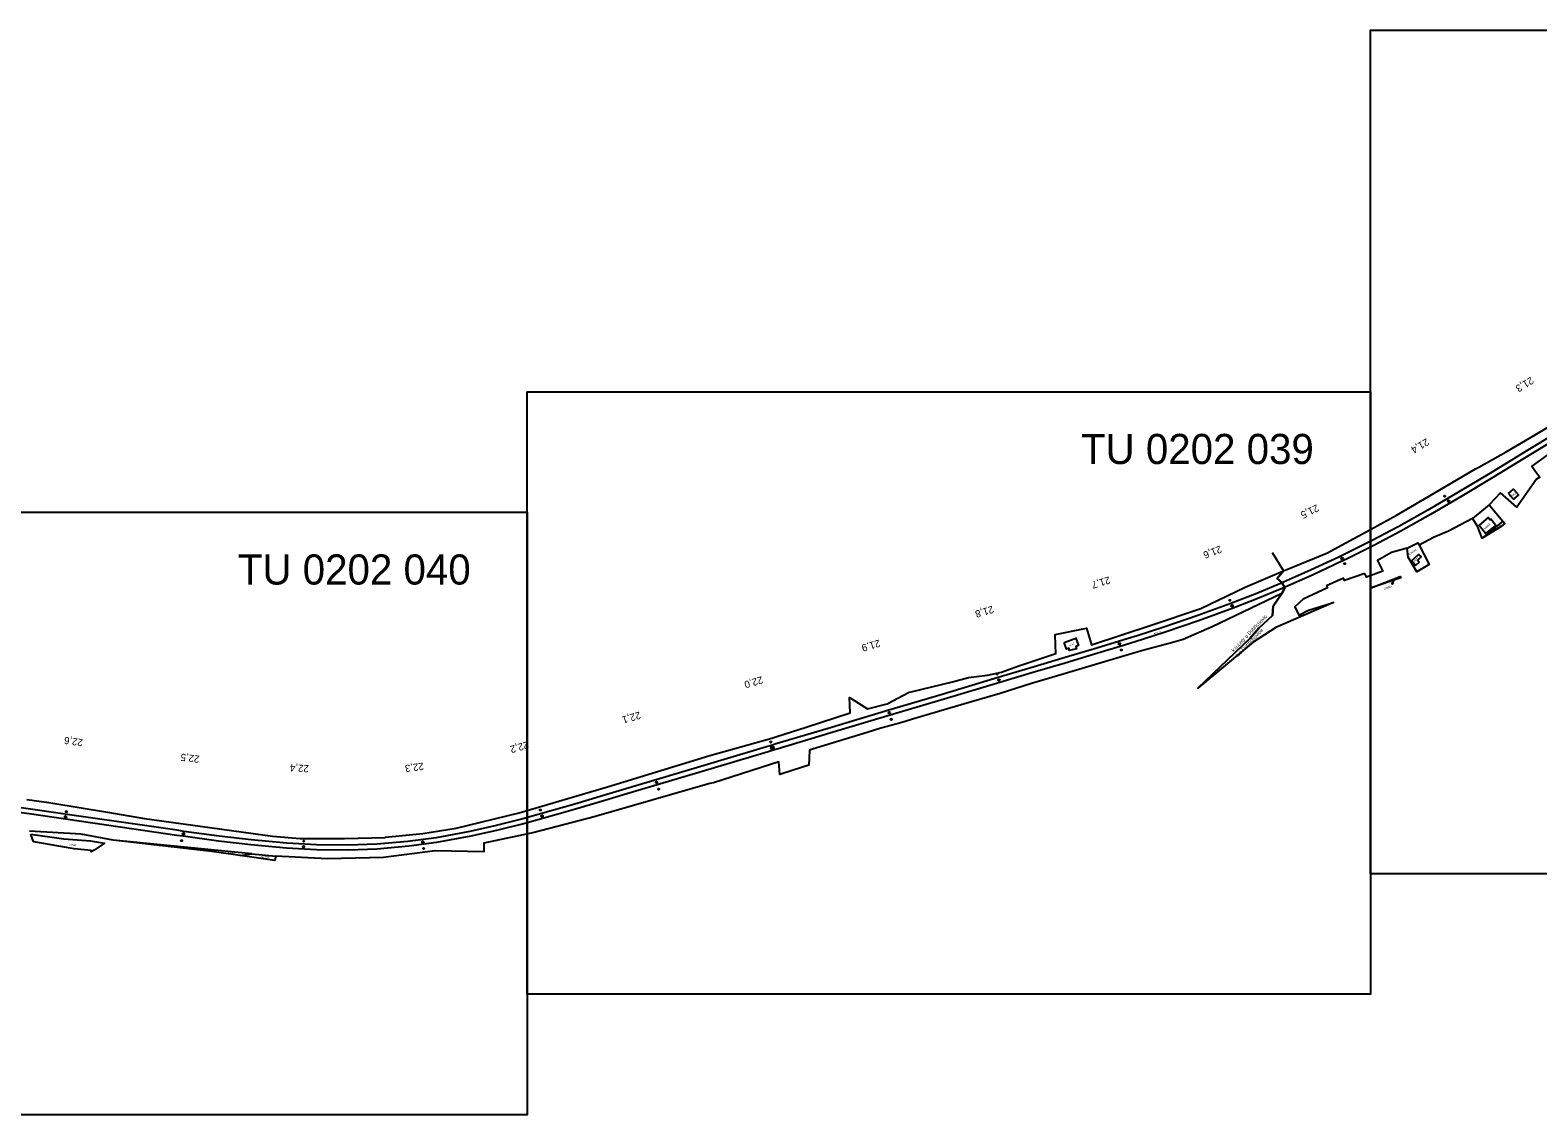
# Model space of a CAD drawing. Extents: x -768800 to -748700, y -1061452 to -1051366.
# Drawn here: x -757513 to -756261, y -1060400 to -1059500 of the extents above; entities that cross this region are included whole.
import ezdxf

# ---------------------------------------------------------------- set-up
doc = ezdxf.new("R2010")
doc.units = 0
for name, color, linetype in [('Vrstva 1', 7, 'Continuous'), ('Vrstva 2', 7, 'Continuous'), ('Vrstva 53', 7, 'Continuous'), ('Vrstva 54', 7, 'Continuous'), ('Vrstva 55', 7, 'Continuous'), ('Vrstva 57', 7, 'Continuous'), ('Vrstva 7', 7, 'Continuous')]:
    doc.layers.add(name, color=color, linetype=linetype)

msp = doc.modelspace()

# ---------------------------------------------------------------- linework, layer by layer
at = {"layer": 'Vrstva 1'}
for p, q in [((-756897.5, -1060093.5), (-756901.4, -1060094.6)), ((-756895.8, -1060097.4), (-756900.1, -1060098.7)), ((-757390.9, -1060168.1), (-757428.4, -1060162.7)), ((-757385.6, -1060168.8), (-757390.9, -1060168.1)), ((-757385.1, -1060164.8), (-757390.6, -1060163.9)), ((-757356.2, -1060172.9), (-757385.6, -1060168.8)), ((-757355.7, -1060168.7), (-757385.1, -1060164.8))]:
    msp.add_line(p, q, dxfattribs=at)
for points in [[(-756400, -1060200), (-756400, -1059500), (-755900, -1059500), (-755900, -1060200), (-756400, -1060200)], [(-757100, -1060300), (-757100, -1059800), (-756400, -1059800), (-756400, -1060300), (-757100, -1060300)], [(-756247.6, -1059835.2), (-756275.6, -1059852.3), (-756300.9, -1059867.8), (-756326, -1059882.9), (-756352.3, -1059898.3), (-756376.5, -1059911.8), (-756399.1, -1059923.7), (-756421.9, -1059935.1), (-756426.3, -1059937.3), (-756449.7, -1059948.2), (-756474.7, -1059959.2), (-756494.4, -1059967.4), (-756515.8, -1059975.8), (-756543.2, -1059985.8), (-756571.6, -1059995.4), (-756593.8, -1060002.5), (-756601.1, -1060004.8), (-756627.1, -1060012.7), (-756650.8, -1060019.8), (-756679.3, -1060028.3), (-756709.1, -1060037.2), (-756755.6, -1060051.1), (-756799.9, -1060064.3), (-756850.3, -1060079.4), (-756892.6, -1060092), (-756897.5, -1060093.5)], [(-756247.5, -1059840.2), (-756273.4, -1059856.1), (-756298.4, -1059871.3), (-756324.2, -1059886.8), (-756350.2, -1059902), (-756374.7, -1059915.6), (-756397.2, -1059927.5), (-756419.8, -1059938.9), (-756424.2, -1059941), (-756447.6, -1059952), (-756472.8, -1059963), (-756492.1, -1059971.1), (-756514.1, -1059979.7), (-756542.7, -1059990.1), (-756570.4, -1059999.5), (-756588.3, -1060005.2), (-756604.9, -1060010.5), (-756626.4, -1060017), (-756653.4, -1060025.1), (-756678.3, -1060032.5), (-756707.6, -1060041.2), (-756753.8, -1060055), (-756798.7, -1060068.4), (-756848.9, -1060083.4), (-756891.6, -1060096.2), (-756895.8, -1060097.4)], [(-757800, -1060400), (-757800, -1059900), (-757100, -1059900), (-757100, -1060400), (-757800, -1060400)], [(-756901.4, -1060094.6), (-756958.7, -1060111.8), (-757020.8, -1060130.3), (-757036.6, -1060135), (-757060.6, -1060142.2), (-757078.3, -1060147.3), (-757103.6, -1060154.4), (-757126.9, -1060160.3), (-757147.5, -1060164.9), (-757175.6, -1060170.1), (-757199, -1060173.2), (-757224.9, -1060175.4), (-757248.6, -1060176.3), (-757274.8, -1060176.1), (-757299.6, -1060174.7), (-757329.2, -1060171.9), (-757355.7, -1060168.7)], [(-757390.6, -1060163.9), (-757427.3, -1060158.6), (-757470.2, -1060152.4), (-757510.3, -1060146.7), (-757531.3, -1060143.7), (-757548.7, -1060141.1), (-757582.8, -1060136.1), (-757619.4, -1060130.7), (-757645.2, -1060126.9), (-757670, -1060123.2), (-757674.9, -1060122.5), (-757704.4, -1060118.1), (-757763.5, -1060109.4)], [(-756900.1, -1060098.7), (-756957.5, -1060115.9), (-757020, -1060134.5), (-757035.7, -1060139.2), (-757060, -1060146.4), (-757077.4, -1060151.4), (-757102.1, -1060158.2), (-757125.6, -1060164.2), (-757146.8, -1060168.9), (-757175.2, -1060174.1), (-757198.2, -1060177.2), (-757224.8, -1060179.5), (-757248.1, -1060180.4), (-757274.9, -1060180.2), (-757299.7, -1060178.8), (-757329.5, -1060176.1), (-757356.2, -1060172.9)], [(-757428.4, -1060162.7), (-757471.9, -1060156.4), (-757511.5, -1060150.6), (-757532, -1060147.7), (-757549.3, -1060145.2), (-757583.5, -1060140.2), (-757619.8, -1060135), (-757646.6, -1060131.2), (-757671.2, -1060127.6), (-757676, -1060126.9), (-757702.8, -1060123), (-757729.2, -1060119.2), (-757731.6, -1060118.9)]]:
    msp.add_lwpolyline(points, dxfattribs=at)
at = {"layer": 'Vrstva 53'}
for points in [[(-757515.4, -1060138.4), (-757497, -1060140.9), (-757493.9, -1060141.3), (-757450, -1060148.6), (-757417.7, -1060154), (-757387.6, -1060158.2), (-757311.4, -1060168.7), (-757288.5, -1060170.6), (-757251.8, -1060170.7), (-757218, -1060169.8), (-757217.6, -1060169.7), (-757186.6, -1060166.7), (-757158.9, -1060162.2), (-757106.6, -1060149.4), (-757033.3, -1060127.9), (-756948.4, -1060101.9), (-756896.9, -1060087.4), (-756892.9, -1060086.1), (-756868.3, -1060078.2), (-756832, -1060066.5), (-756832.6, -1060053.7), (-756817.6, -1060063.1), (-756801.3, -1060058.9), (-756782.8, -1060049.4), (-756781.2, -1060049), (-756747, -1060040.6), (-756733.8, -1060037), (-756717.8, -1060035.1), (-756706.2, -1060032.7), (-756704.1, -1060031.9), (-756691.8, -1060027.4), (-756661.2, -1060017.1), (-756661.4, -1060010.3), (-756661.7, -1060001.5), (-756635.8, -1059996.1), (-756631.7, -1060010), (-756582.1, -1059993.6), (-756540.9, -1059980), (-756504.1, -1059962.3), (-756472.3, -1059948.7), (-756469.5, -1059947.6), (-756435.8, -1059933.6), (-756424, -1059927.2), (-756399.9, -1059914.2), (-756377.8, -1059902.2), (-756347.1, -1059884.3), (-756312.9, -1059864.1), (-756310, -1059862.5), (-756287.4, -1059849.9), (-756263.4, -1059835.9), (-756241.4, -1059822.7)], [(-756253, -1059852.5), (-756266, -1059861.9), (-756263.5, -1059865.4), (-756259.5, -1059871), (-756262.1, -1059872.6), (-756278.4, -1059895.7), (-756292.1, -1059883.9), (-756301.4, -1059893.9), (-756290, -1059907.3), (-756288.5, -1059909.4), (-756291.4, -1059911.9), (-756307.2, -1059921.5), (-756311.1, -1059911.6), (-756315.3, -1059905.1), (-756335.1, -1059915.8), (-756347.6, -1059921), (-756359.7, -1059927.4), (-756351.2, -1059943.4), (-756361.5, -1059949.4), (-756368.7, -1059937.2), (-756369.6, -1059929.9), (-756382.5, -1059933.3), (-756394.1, -1059940), (-756389.7, -1059948.9), (-756403.3, -1059954), (-756404.6, -1059950.8)], [(-756404.6, -1059950.8), (-756421.6, -1059956.5), (-756422.4, -1059954.7), (-756436.5, -1059961.1), (-756435.8, -1059962.8), (-756455.9, -1059972), (-756462.9, -1059978.4), (-756459.4, -1059985.4), (-756451.4, -1059981.2), (-756430.7, -1059974.9), (-756478.6, -1059995.6), (-756497.3, -1060007.8), (-756543.3, -1060045.9), (-756500.1, -1060004.9), (-756492.8, -1059996.3), (-756481.4, -1059985.7), (-756480.8, -1059977.8), (-756473.5, -1059967.4), (-756531.5, -1059995.2), (-756555.6, -1060005.6), (-756565.3, -1060008.4), (-756590, -1060014.9), (-756630.9, -1060027.2), (-756655.1, -1060034.4), (-756681.4, -1060042.2), (-756707.5, -1060050.5)], [(-756399.5, -1059962.8), (-756375.3, -1059953.4), (-756374.8, -1059954.4), (-756399.5, -1059962.8)], [(-756707.5, -1060050.5), (-756739.7, -1060059.9), (-756780.2, -1060071.8), (-756787, -1060073.9), (-756794, -1060075.8), (-756806.5, -1060079.2), (-756817.9, -1060082.7), (-756830.4, -1060086.6), (-756863.1, -1060096.7), (-756865.8, -1060097.5), (-756866, -1060104), (-756866.2, -1060109.8), (-756879.1, -1060113.9), (-756890.4, -1060117.7), (-756891, -1060107.2), (-756945.3, -1060124.4), (-756948.3, -1060125.2), (-757044.3, -1060152.6), (-757094.3, -1060165.8), (-757135.9, -1060174.5), (-757136, -1060181.8), (-757176.4, -1060180.9), (-757219.2, -1060186.4), (-757265.9, -1060187.6), (-757308.7, -1060185.5), (-757309.5, -1060188.9), (-757338.3, -1060184.9), (-757361.9, -1060181.6), (-757443.6, -1060172), (-757470.4, -1060167), (-757513.1, -1060164.5)], [(-757512.1, -1060167.1), (-757484.7, -1060171), (-757462.5, -1060172.6), (-757451, -1060174.5), (-757459.6, -1060180.3), (-757462, -1060181.9), (-757461.9, -1060180.6), (-757476.1, -1060179.3), (-757509.6, -1060173.6), (-757510.3, -1060172.2), (-757512.1, -1060167.1)]]:
    msp.add_lwpolyline(points, dxfattribs=at)
at = {"layer": 'Vrstva 54'}
msp.add_line((-756380.8, -1059958.7), (-756381.9, -1059959.7), dxfattribs=at)
msp.add_lwpolyline([(-756380.6, -1059955.9), (-756381.9, -1059959.7), (-756382.2, -1059958.2)], dxfattribs=at)
at = {"layer": 'Vrstva 55'}
for p, q in [((-756301.4, -1059893.9), (-756315.3, -1059905.1)), ((-756290, -1059907.3), (-756307.2, -1059921.5)), ((-757328.6, -1060183.5), (-757443.6, -1060172))]:
    msp.add_line(p, q, dxfattribs=at)
for points in [[(-756285.4, -1059884.5), (-756281.2, -1059880.8), (-756277.1, -1059885.5), (-756281.3, -1059889.2), (-756285.4, -1059884.5)], [(-756304.1, -1059917.6), (-756295.9, -1059910.9), (-756300.1, -1059905.8), (-756300.8, -1059906.3), (-756302.3, -1059904.4), (-756309.9, -1059910.6), (-756304.1, -1059917.6)], [(-756481.7, -1059933.3), (-756472.3, -1059948.7), (-756477.5, -1059954.9), (-756473.5, -1059958.4), (-756471.1, -1059962.7)], [(-756369.6, -1059929.9), (-756360.6, -1059925.4), (-756359.7, -1059927.4)], [(-756366, -1059940.4), (-756360, -1059935.1), (-756357.8, -1059937.1), (-756360.8, -1059939.9), (-756359.5, -1059941.4), (-756362.7, -1059944.1), (-756366, -1059940.4)], [(-756473.5, -1059967.4), (-756471.1, -1059962.7), (-756473.5, -1059958.4), (-756477.5, -1059954.9), (-756472.3, -1059948.7)], [(-756471.1, -1059962.7), (-756473.5, -1059967.4), (-756480.8, -1059977.8), (-756481.4, -1059985.7), (-756492.8, -1059996.3), (-756500.1, -1060004.9), (-756543.3, -1060045.9)], [(-756654.3, -1060008), (-756644.6, -1060004.5), (-756642.4, -1060010.6), (-756644.5, -1060011.4), (-756643.9, -1060013.3), (-756649.8, -1060014.7), (-756650.4, -1060012.8), (-756652.3, -1060013.5), (-756654.3, -1060008)], [(-757338.3, -1060184.9), (-757328.6, -1060183.5), (-757308.7, -1060185.5)]]:
    msp.add_lwpolyline(points, dxfattribs=at)
at = {"layer": 'Vrstva 7'}
for p, q in [((-756338.3, -1059886.7), (-756338.4, -1059886.7)), ((-756421.3, -1059942.7), (-756421.4, -1059942.7)), ((-756516.7, -1059973.1), (-756516.8, -1059973.1)), ((-756606.8, -1060014.3), (-756606.9, -1060014.3)), ((-756709.8, -1060034.4), (-756709.9, -1060034.4)), ((-756797.7, -1060071.9), (-756797.8, -1060071.9)), ((-756897.8, -1060090.7), (-756897.9, -1060090.7)), ((-756990.8, -1060129.8), (-756990.9, -1060129.8)), ((-757482.6, -1060148.4), (-757482.7, -1060148.4)), ((-757089.1, -1060147), (-757089.2, -1060147.1)), ((-757386.9, -1060172.5), (-757387, -1060172.5)), ((-757285.3, -1060172.9), (-757285.4, -1060172.9)), ((-757185.9, -1060179), (-757186, -1060179))]:
    msp.add_line(p, q, dxfattribs=at)
for centre, radius in [((-756338.4, -1059886.7), 0.5), ((-756335.1, -1059890.8), 0.75), ((-756423.5, -1059938.3), 0.75), ((-756421.4, -1059942.7), 0.5), ((-756516.7, -1059973.1), 0.5), ((-756514.9, -1059977.7), 0.75), ((-756608.4, -1060009.3), 0.75), ((-756606.8, -1060014.3), 0.5), ((-756709.9, -1060034.4), 0.5), ((-756708.4, -1060039.2), 0.75), ((-756799.4, -1060066.4), 0.75), ((-756797.8, -1060071.9), 0.5), ((-756897.8, -1060090.7), 0.5), ((-756896.5, -1060095.4), 1.25), ((-756896.5, -1060095.4), 0.752), ((-756992.6, -1060124.1), 0.75), ((-756990.9, -1060129.8), 0.5), ((-757482.6, -1060148.4), 0.5), ((-757089.1, -1060147.1), 0.5), ((-757483.2, -1060152.7), 0.75), ((-757087.7, -1060152.1), 0.75), ((-757386.9, -1060172.5), 0.5), ((-757385.4, -1060166.8), 0.75), ((-757285.4, -1060172.9), 0.5), ((-757186.7, -1060173.6), 0.75), ((-757285.6, -1060177.5), 0.75), ((-757185.9, -1060179), 0.5)]:
    msp.add_circle(centre, radius, dxfattribs=at)

# ---------------------------------------------------------------- texts
at = {"layer": 'Vrstva 2'}
for s, p in [('TU 0202 039', (-756640.3, -1059860)), ('TU 0202 040', (-757340.2, -1059960))]:
    msp.add_text(s, height=25, dxfattribs=at).set_placement(p)
at = {"layer": 'Vrstva 55'}
for s, rotation, p in [('k.ú.Lety u Dobřichovic', 46.277, (-756513.7, -1060016.1)), ('k.ú.Dobřichovice', 46.6281, (-756509.9, -1060020.4))]:
    msp.add_text(s, height=3, rotation=rotation, dxfattribs=at).set_placement(p)
at = {"layer": 'Vrstva 57'}
for s, rotation, p in [('2999/2', 207.2707, (-756279.6, -1059883.5)), ('2999/4', 223.9848, (-756301.4, -1059909)), ('2999/28', 207.7537, (-756290.9, -1059909.9)), ('2999/20', 211.0489, (-756362.2, -1059930.5)), ('2999/8', 221.3034, (-756360.5, -1059937)), ('2999/27', 201.6834, (-756382.5, -1059960.5)), ('1376/4', 195.0903, (-756573.9, -1059998.5)), ('1377', 196.9157, (-756646, -1060008.2)), ('1659/1', 172.0877, (-757474, -1060175.7)), ('1658/4', 173.1674, (-757342.3, -1060182.4)), ('1657/6', 172.3345, (-757314.4, -1060185.9))]:
    msp.add_text(s, height=1.5, rotation=rotation, dxfattribs=at).set_placement(p)
at = {"layer": 'Vrstva 7'}
for s, rotation, p in [('21,3', 211.5043, (-756266.9, -1059787.4)), ('21,4', 210.2639, (-756353.6, -1059838.5)), ('21,5', 206.421, (-756444.7, -1059893.3)), ('21,6', 201.3894, (-756524.9, -1059927.5)), ('21,7', 196.9831, (-756617.1, -1059953.2)), ('21,8', 196.6203, (-756713.8, -1059977.5)), ('21,9', 196.6398, (-756808, -1060005.6)), ('22,0', 196.5842, (-756905.4, -1060036)), ('22,1', 196.623, (-757006.8, -1060065.3)), ('22,6', 171.8255, (-757468.5, -1060088.4)), ('22,2', 195.5433, (-757099.7, -1060090)), ('22,5', 173.0799, (-757371.8, -1060102.1)), ('22,4', 176.8513, (-757281.1, -1060109.9)), ('22,3', 187.7085, (-757186.3, -1060107.7))]:
    msp.add_text(s, height=6, rotation=rotation, dxfattribs=at).set_placement(p)

doc.saveas('drawing.dxf')
